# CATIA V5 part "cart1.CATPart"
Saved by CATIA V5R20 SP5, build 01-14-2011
Part number: 保温杯固定杆
Material "Grey Sky"
Bounding box of the stored display mesh (mm): x -5 to 5, y -7.5 to 7.5, z 0 to 210
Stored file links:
  E:\设计\180212313林恺昇\cart1.CATPart
  E:\设计\180212313林恺昇\Product1.CATProduct
  E:\设计\180212313林恺昇\cup.CATPart
  C:\Program Files\Dassault Systemes\B20\intel_a\startup\materials\Catalog.CATMaterial
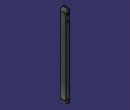
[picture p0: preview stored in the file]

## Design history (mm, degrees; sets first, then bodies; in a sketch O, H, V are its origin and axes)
Body1 (main body)
  Sketch1 on xy-plane, origin (0, 0, 0), H (1, 0, 0), V (0, 1, 0)
    line L1 (5, 7.5) -> (5, -7.5)
    line L2 (5, -7.5) -> (-5, -7.5)
    line L3 (-5, -7.5) -> (-5, 7.5)
    line L4 (-5, 7.5) -> (5, 7.5)
    length L3 = 15
    length L2 = 10
    vertical: L1 V, L3 V
    horizontal: L2 H, L4 H
    equidistance: L1 L3 O, L2 L4 O
  Pad1: profile Sketch1, direction (0, 0, 1), length 210
  Sketch2 on face of Pad1 from Sketch1.L4, origin (0, 7.5, 0), H (-1, 0, 0), V (0, 0, 1)
    circle A1 centre (0, 200) radius 2.5
    point P1 (0, 200)
    circle A2 centre (0, 8) radius 2.5
    point P2 (0, 8)
    reference projected line E1 (-5, 210) -> (5, 210) from edge [face of Pad1 from Sketch1.L4 | end face of Pad1]
    circle A3 centre (0, 183.6185) radius 2.5
    point P3 (0, 183.6185)
    radius A1 = 2.5
    radius A2 = 2.5
    distance P2 P1 = 192
    distance P1 E1 = 10
    radius A3 = 2.5
    coincidence: P1 V, P2 V, P3 V
  Pocket1: profile Sketch2, direction (0, -1, 0), length 20
  Fillet1: radius 7, on edge [start face of Pad1 | face of Pad1 from Sketch1.L1]
  Fillet2: radius 7, on edge [face of Pad1 from Sketch1.L1 | end face of Pad1]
